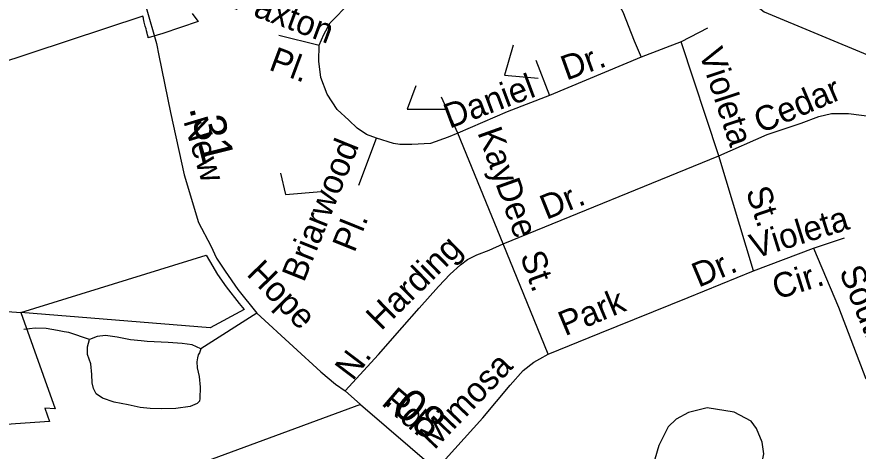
# Model space of a CAD drawing. Extents: x 2315291 to 2336543, y 597177 to 615230.
# Drawn here: x 2318553 to 2321792, y 599047 to 600720 of the extents above; entities that cross this region are included whole.
import ezdxf

# ---------------------------------------------------------------- set-up
doc = ezdxf.new("R2010")
doc.units = 0
for name, color, linetype in [('Exist Boundary Political City Limit New', 7, 'Continuous'), ('Exist Hydrographic Misc Water Feature', 7, 'Continuous'), ('Exist Road Non-System Type 51', 7, 'Continuous'), ('Exist Road Non-System Type 51 Label', 7, 'Continuous'), ('Exist Road Secondary Mileage Hundredths English Label', 7, 'Continuous'), ('Exist Road Secondary Type 51 Attributed', 7, 'Continuous'), ('Exist Road Secondary Type 51 Label', 7, 'Continuous'), ('Map Preparation Boundary City Limit Buffer Line', 7, 'Continuous')]:
    doc.layers.add(name, color=color, linetype=linetype)

msp = doc.modelspace()

# ---------------------------------------------------------------- linework, layer by layer
at = {"layer": 'Exist Boundary Political City Limit New'}
for points in [[(2319228.8, 600733.2), (2319246.5, 600708.2), (2319251.2, 600701.3), (2319116, 600655.1), (2319059.5, 600638.4), (2319058.5, 600642.8), (2319056.5, 600650.6), (2319055, 600657.4), (2319052.8, 600666.1), (2319050.8, 600673.8), (2319048, 600683.5), (2319044, 600699), (2319042.5, 600705.8), (2319041.2, 600711.7), (2319040.5, 600714.6), (2319039.5, 600718.5), (2319038.8, 600721.7), (2318179, 600438.4)], [(2318568.5, 599581.4), (2319282.8, 599801.6), (2319295, 599780.3), (2319325.8, 599727.6), (2319359.2, 599680.2), (2319409.2, 599615.8), (2319428.5, 599592.8), (2319298.2, 599522.6), (2318568.5, 599581.4)], [(2318568.5, 599581.4), (2318700.5, 599210), (2318661, 599213.2), (2318679.8, 599162), (2318547.8, 599152.8), (2318426, 599144.2), (2318396.2, 599234.6), (2317998.2, 599253.6), (2318517.8, 599585.9), (2318568.5, 599581.4)]]:
    msp.add_lwpolyline(points, dxfattribs=at)
at = {"layer": 'Exist Hydrographic Misc Water Feature'}
msp.add_lwpolyline([(2320143.8, 601160.7), (2320239.2, 601209.6), (2320544.1, 601304.9), (2320856.8, 601404.2), (2320910.3, 601258.7), (2320957.9, 601113.2), (2321185.3, 600931.8), (2321429.5, 600738.5), (2321842.9, 600567.2), (2322346.9, 600362.8), (2322643, 600741.7), (2323035.1, 601251.6), (2323257.7, 601549.8)], dxfattribs=at)
at = {"layer": 'Exist Road Non-System Type 51'}
for p, q in [((2321211.8, 600676.1), (2321110.4, 600623.3)), ((2319561.6, 600649.1), (2319717.4, 600611.1)), ((2321110.4, 600623.3), (2320956.3, 600564.5)), ((2321255.4, 600184.4), (2321110.4, 600623.3)), ((2320956.3, 600564.5), (2320603.5, 600416.4)), ((2320550.8, 600552.3), (2320603.5, 600416.4)), ((2320250.7, 600272.3), (2320187.8, 600410.3)), ((2319869.6, 600071.9), (2319938.4, 600252)), ((2320425.4, 599846.2), (2320250.7, 600272.3)), ((2320425.4, 599846.2), (2321255.4, 600184.4)), ((2321389.2, 599741.4), (2321255.4, 600184.4)), ((2321620.3, 599828.7), (2321739.3, 599869.2)), ((2320598.4, 599420.9), (2320425.4, 599846.2)), ((2321389.2, 599741.4), (2321620.3, 599828.7)), ((2319477.8, 599578.5), (2319261.3, 599441.6))]:
    msp.add_line(p, q, dxfattribs=at)
for points in [[(2319717.4, 600611.1), (2319735.7, 600651.7), (2319760, 600696.4), (2319835, 600773.5), (2319942.5, 600834.3), (2320086.5, 600899.2), (2320256.8, 600988.5), (2320370.3, 601035.2), (2320417, 601044.3), (2320451.4, 601039.2), (2320524.4, 601024), (2320607.6, 600993.6)], [(2320607.6, 600993.6), (2320737.3, 600938.8), (2320781.9, 600910.4), (2320816.4, 600871.9), (2320855.3, 600794.2), (2320885.9, 600738.4), (2320929, 600626.9), (2320956.3, 600564.5)], [(2319938.4, 600252), (2319899.9, 600266.2), (2319863.2, 600291.7), (2319830.9, 600321.4), (2319786.4, 600362.6), (2319747.8, 600421.4), (2319723.5, 600486.4), (2319715.4, 600549.3), (2319717.4, 600611.1)], [(2320603.5, 600416.4), (2320441.3, 600353.5), (2320250.7, 600272.3)], [(2321255.4, 600184.4), (2321441.9, 600266.9), (2321571.7, 600310.2), (2321640.6, 600335.9), (2321689.3, 600348.1), (2321754.2, 600348.1), (2321844.7, 600335.9), (2321950.2, 600306.1), (2322019.1, 600264.2), (2322074.5, 600202), (2322170.5, 600100.5), (2322413.8, 599803)], [(2320250.7, 600272.3), (2320214.2, 600256.1), (2320145.3, 600231.7), (2320074.3, 600227.7), (2320027.9, 600228), (2320003.3, 600231.7), (2319938.4, 600252)], [(2319817.5, 599280.1), (2319945.5, 599419.5), (2320036.1, 599523.7), (2320102.3, 599598.1), (2320176.7, 599681.9), (2320221.3, 599729.3), (2320260.5, 599765.1), (2320287.5, 599785.4), (2320324, 599803), (2320371.3, 599821.9), (2320425.4, 599846.2)], [(2321620.3, 599828.7), (2321716.3, 599601.4), (2321821.7, 599325.5)], [(2320598.4, 599420.9), (2320797.1, 599502), (2321137.8, 599638.6), (2321389.2, 599741.4)], [(2318735.1, 599507.5), (2318710.2, 599511.7), (2318666.1, 599519.3), (2318624.1, 599520.8), (2318580.2, 599516.2)], [(2318833.4, 599477.2), (2318754.2, 599504.2), (2318735.1, 599507.5)], [(2319261.3, 599441.6), (2319255.9, 599426.3), (2319251.7, 599417.9), (2319248.6, 599406.4), (2319246, 599392), (2319247.3, 599367.9), (2319254.9, 599334.9), (2319258.7, 599294.2), (2319257.5, 599249.8), (2319255.9, 599239.9), (2319247.4, 599230.7), (2319220.6, 599219.3), (2319164.8, 599211.6), (2319108.9, 599210.4), (2319067, 599211.6), (2319027.6, 599215.4), (2318981.9, 599225.6), (2318928.6, 599235.8), (2318882.9, 599251), (2318858.8, 599268.8), (2318848.6, 599289.1), (2318843.5, 599310.7), (2318842.3, 599342.5), (2318838.4, 599383.2), (2318825.7, 599420), (2318825.1, 599449.7), (2318833.4, 599477.2)], [(2319261.3, 599441.6), (2319228.3, 599456.8), (2319190.2, 599461.9), (2319135.6, 599465.7), (2319055.6, 599469.6), (2319031.5, 599472.1), (2318990.8, 599475.9), (2318940, 599486.1), (2318894.3, 599492.4), (2318862.6, 599488.6), (2318833.4, 599477.2)], [(2320167.2, 598977.2), (2320347, 599176), (2320452.4, 599301.8), (2320502.5, 599358.6), (2320543, 599389.8), (2320566, 599403.3), (2320598.4, 599420.9)], [(2321245.9, 598342.2), (2321413.5, 598963), (2321428.4, 599037.4), (2321421.6, 599082), (2321400, 599134.8), (2321379.7, 599163.2), (2321314.1, 599198), (2321210.8, 599214.6), (2321139.1, 599197), (2321091.8, 599171.3), (2321060.7, 599141.6), (2321024.2, 599069.9), (2320985, 598933.3)]]:
    msp.add_lwpolyline(points, dxfattribs=at)
at = {"layer": 'Exist Road Non-System Type 51 Label'}
for points in [[(2320463.4, 600610.3), (2320429.9, 600494.8), (2320560.2, 600483.7)], [(2320088.8, 600453.6), (2320055.3, 600364.2), (2320207.9, 600364.2)], [(2319568.3, 600118.3), (2319586.9, 600036.3), (2319724.7, 600047.5)], [(2319875.9, 599227.8), (2318529.3, 598730.4), (2318439.4, 598697), (2318076.9, 598562.3), (2317685.5, 598416.9), (2317200.8, 598235.4), (2317018.9, 598167.2), (2317008.3, 598164.2), (2316938.9, 598144.3), (2316832.2, 598110), (2316707.5, 598081.8), (2316590.7, 598067.7), (2316575.1, 598066.8), (2316290.6, 598049.6), (2316055, 598033.5), (2315908, 598023.4), (2315833.5, 598018.4), (2315744.5, 597990.8)]]:
    msp.add_lwpolyline(points, dxfattribs=at)
at = {"layer": 'Exist Road Secondary Type 51 Attributed'}
for points in [[(2318498.2, 601663.5), (2318542.1, 601594.9), (2318660.7, 601409.7), (2318820.7, 601214.7), (2318885.4, 601114.3), (2318927.3, 601036.8), (2318961.6, 600970.7), (2319008.2, 600873.1), (2319051.3, 600756.2), (2319090.9, 600617.6), (2319100.2, 600571.4), (2319144.5, 600351.3), (2319197.8, 600111.2), (2319253, 599927.3), (2319300.4, 599837.8), (2319321.6, 599790.1), (2319355.9, 599740.5), (2319403.5, 599670), (2319477.8, 599578.5), (2319616.8, 599450.8), (2319723.5, 599353.6), (2319780.6, 599306), (2319817.5, 599280.1), (2319875.9, 599227.8)], [(2319875.9, 599227.8), (2320167.2, 598977.2), (2320407.2, 598770.3), (2320440.3, 598727), (2320562.9, 598622), (2320664.7, 598550.5), (2320712, 598524.8), (2320768.7, 598495), (2320841.7, 598463.2), (2321000.7, 598414.1)]]:
    msp.add_lwpolyline(points, dxfattribs=at)
at = {"layer": 'Map Preparation Boundary City Limit Buffer Line'}
for points in [[(2319228.8, 600733.2), (2319246.5, 600708.2), (2319251.2, 600701.3), (2319116, 600655.1), (2319059.5, 600638.4), (2319058.5, 600642.8), (2319056.5, 600650.6), (2319055, 600657.4), (2319052.8, 600666.1), (2319050.8, 600673.8), (2319048, 600683.5), (2319044, 600699), (2319042.5, 600705.8), (2319041.2, 600711.7), (2319040.5, 600714.6), (2319039.5, 600718.5), (2319038.8, 600721.7), (2318179, 600438.4)], [(2318568.5, 599581.4), (2319282.8, 599801.6), (2319295, 599780.3), (2319325.8, 599727.6), (2319359.2, 599680.2), (2319409.2, 599615.8), (2319428.5, 599592.8), (2319298.2, 599522.6), (2318568.5, 599581.4)], [(2318568.5, 599581.4), (2318700.5, 599210), (2318661, 599213.2), (2318679.8, 599162), (2318547.8, 599152.8), (2318426, 599144.2), (2318396.2, 599234.6), (2317998.2, 599253.6), (2318517.8, 599585.9), (2318568.5, 599581.4)]]:
    msp.add_lwpolyline(points, dxfattribs=at)

# ---------------------------------------------------------------- texts
at = {"layer": 'Exist Road Non-System Type 51 Label'}
for s, rotation, p in [('Paxton', 339.5208, (2319380.5, 600753.5)), ('Pl.', 339.5208, (2319519.3, 600517.3)), ('Violeta', 288.332, (2321177.7, 600582.5)), ('Dr.', 19.808, (2320668.8, 600473.9)), ('Daniel', 20.5363, (2320218.8, 600288.5)), ('Cedar', 23.1549, (2321415.9, 600269.6)), ('Kay', 289.6666, (2320325.2, 600274.9)), ('Briarwood', 68.0781, (2319658.3, 599694.4)), ('Dee', 289.6072, (2320394.6, 600078.8)), ('Dr.', 21.9906, (2320591.5, 599937.4)), ('St.', 288.7948, (2321358, 600049.1)), ('Violeta', 17.3564, (2321393, 599787.9)), ('Pl.', 68.0781, (2319852.6, 599808.6)), ('Harding', 44.4553, (2319955.1, 599508.3)), ('St.', 289.6072, (2320489.3, 599799.7)), ('Dr.', 22.7826, (2321177.3, 599676.5)), ('Cir.', 17.3564, (2321478.6, 599630.3)), ('South', 292.2219, (2321717.1, 599740.1)), ('Park', 22.5981, (2320663.1, 599489.6)), ('N.', 52.8375, (2319846.4, 599315.1)), ('Mimosa', 46.2321, (2320160.3, 599049.9))]:
    msp.add_text(s, height=95, rotation=rotation, dxfattribs=at).set_placement(p)
at = {"layer": 'Exist Road Secondary Mileage Hundredths English Label'}
for s, rotation, p in [('.31', 284.069, (2319215.9, 600369)), ('.08', 319.4624, (2319958.7, 599235.9))]:
    msp.add_text(s, height=125, rotation=rotation, dxfattribs=at).set_placement(p)
at = {"layer": 'Exist Road Secondary Type 51 Label'}
for s, rotation, p in [('New', 286.7033, (2319193.5, 600318.9)), ('Hope', 314.2785, (2319433.8, 599726.8)), ('Rd.', 319.4624, (2319952.9, 599228.6))]:
    msp.add_text(s, height=95, rotation=rotation, dxfattribs=at).set_placement(p)

doc.saveas('drawing.dxf')
